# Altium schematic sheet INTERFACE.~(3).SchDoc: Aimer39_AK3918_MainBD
size 431 x 279 mm; Revision: 1.2.1; Release Date: 2014-05-28; SchModifyDate: 2020.11.1; PCBVersion: V1.0.0; PCBPartNumber: EVB_PHY_SZ18201; 版本号: V1.0.0
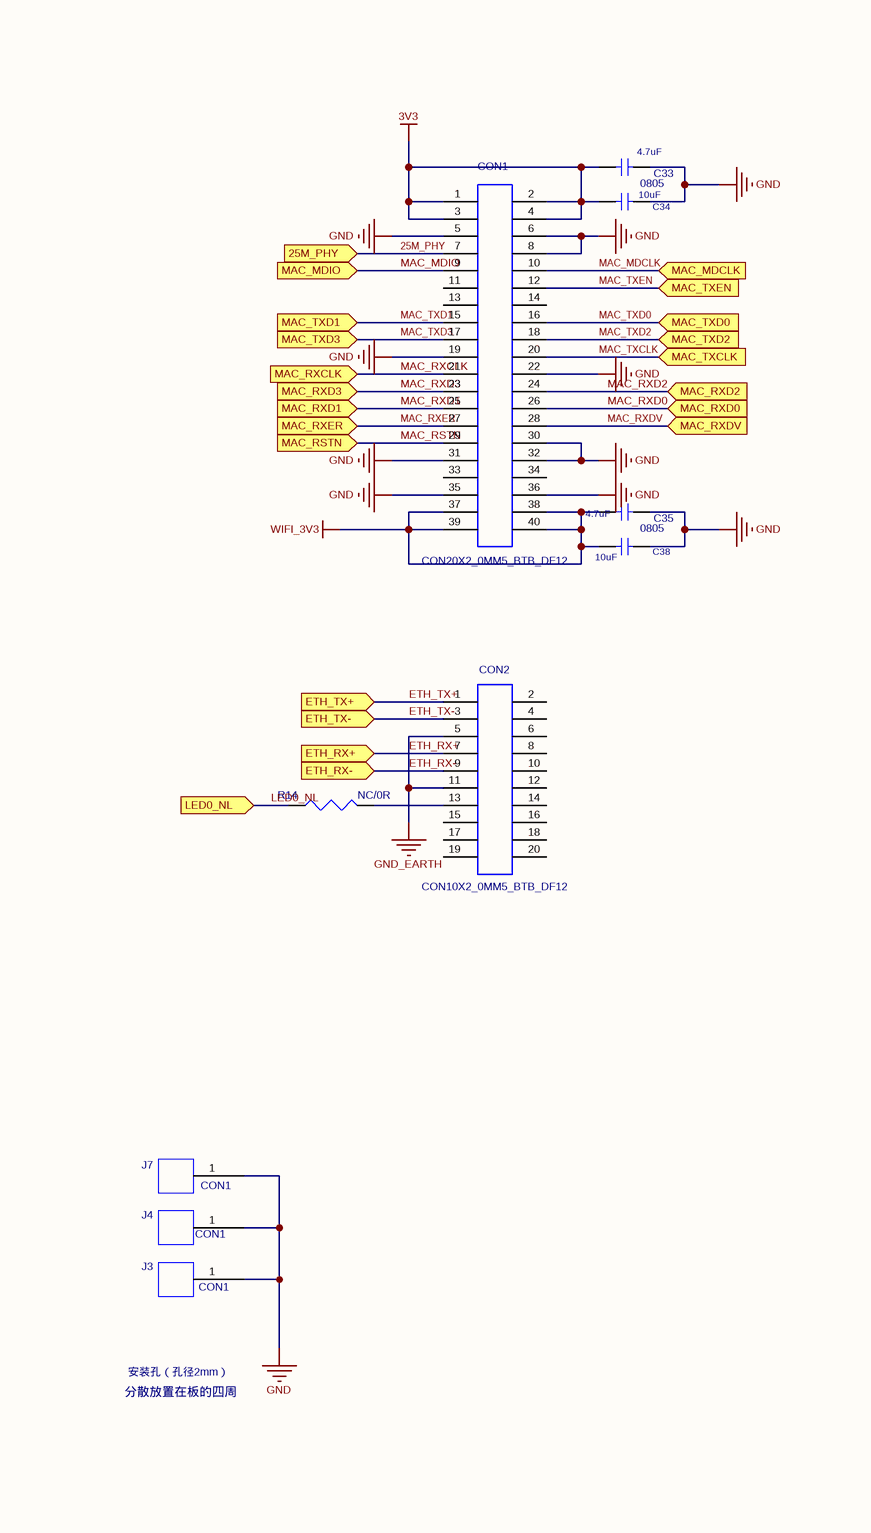
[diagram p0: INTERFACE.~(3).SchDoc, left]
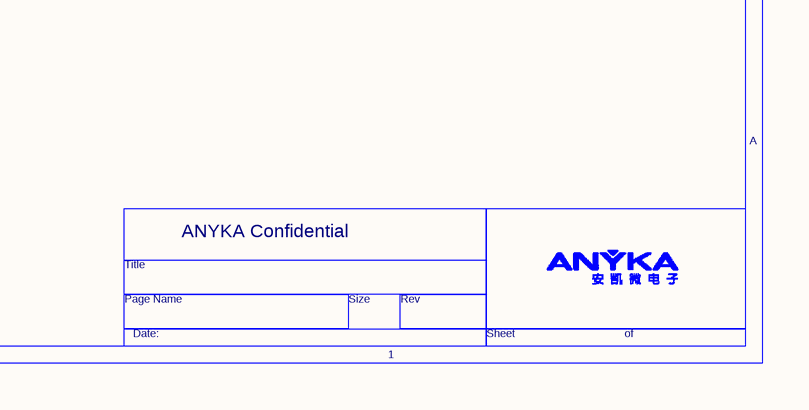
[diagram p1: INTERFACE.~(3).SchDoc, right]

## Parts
C33  value 4.7uF  [C0603]  (hidden comment: C0603)
C34  value 10uF  [C0805]  (hidden comment: C0805)
C35  value 4.7uF  [C0603]  (hidden comment: C0603)
C38  value 10uF  [C0805]  (hidden comment: C0805)
CON1  CON20X2_0MM5_BTB_DF12  [CON20X2_0MM5_BTB_DF12]
CON2  CON10X2_0MM5_BTB_DF12  [CON10X2_0MM5_BTB_DF12]
J3  CON1  [H_2MM2_4MM]
J4  CON1  [H_2MM2_4MM]
J7  CON1  [H_2MM2_4MM]
R14  value NC/0R  [R0603]  (hidden comment: R0603)

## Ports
25M_PHY, ETH_RX+, ETH_RX-, ETH_TX+, ETH_TX-, LED0_NL, MAC_MDCLK, MAC_MDIO, MAC_RSTN, MAC_RXCLK, MAC_RXD0, MAC_RXD1, MAC_RXD2, MAC_RXD3, MAC_RXDV, MAC_RXER, MAC_TXCLK, MAC_TXD0, MAC_TXD1, MAC_TXD2, MAC_TXD3, MAC_TXEN

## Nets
3V3: C33.2 C34.2 CON1.1 CON1.2 CON1.3 CON1.4
ETH_RX+: CON2.5 CON2.7 CON2.9 CON2.11 ; port ETH_RX+, port ETH_RX-  [also labelled ETH_RX-, GND_EARTH]
GND: C33.1 C34.1 C35.1 C38.1 CON1.5 CON1.6 CON1.8 CON1.19 CON1.22 CON1.30 CON1.31 CON1.32 CON1.35 CON1.36 J3.1 J4.1 J7.1
WIFI_3V3: C35.2 C38.2 CON1.37 CON1.38 CON1.39 CON1.40
25M_PHY: CON1.7 ; port 25M_PHY
ETH_TX+: CON2.1 ; port ETH_TX+
ETH_TX-: CON2.3 ; port ETH_TX-
LED0_NL: R14.2 ; port LED0_NL
MAC_MDCLK: CON1.10 ; port MAC_MDCLK
MAC_MDIO: CON1.9 ; port MAC_MDIO
MAC_RSTN: CON1.29 ; port MAC_RSTN
MAC_RXCLK: CON1.21 ; port MAC_RXCLK
MAC_RXD0: CON1.26 ; port MAC_RXD0
MAC_RXD1: CON1.25 ; port MAC_RXD1
MAC_RXD2: CON1.24 ; port MAC_RXD2
MAC_RXD3: CON1.23 ; port MAC_RXD3
MAC_RXDV: CON1.28 ; port MAC_RXDV
MAC_RXER: CON1.27 ; port MAC_RXER
MAC_TXCLK: CON1.20 ; port MAC_TXCLK
MAC_TXD0: CON1.16 ; port MAC_TXD0
MAC_TXD1: CON1.15 ; port MAC_TXD1
MAC_TXD2: CON1.18 ; port MAC_TXD2
MAC_TXD3: CON1.17 ; port MAC_TXD3
MAC_TXEN: CON1.12 ; port MAC_TXEN
NetCON2_13: CON2.13 R14.1

Not connected (* = marked no-connect by the designer): CON1 11 13 14 33 34; CON2 2 4 6 8 10 12 14 15 16 17 18 19 20

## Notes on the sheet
- 安装孔（孔径2mm）
- 分散放置在板的四周
- A
- Title
- ANYKA Confidential
- Page Name
- Date:
- Size
- 1
- Rev
- Sheet
- of

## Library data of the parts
C33 C35 = C0603: Part Number_AK: CC0301064XX; SOURCE_PATH: E:\工作目录\ORCAD原理图库\ORCAD元件库\电容.OLB
C34 C38 = C0805: C/C,10uF,16V,+/-10%,0805; Part Number_AK: CC0501061XX; SOURCE_PATH: E:\工作目录\ORCAD原理图库\ORCAD元件库\电容.OLB
J3 J4 J7 = CON1: Source_Path: D:\CADENCE\SPB_16.3\TOOLS\CAPTURE\LIBRARY\CONNECTOR.OLB
R14 = R0603: Res,0R,1/10W,+/-5%,0603; Part Number_AK: CR0300000XX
